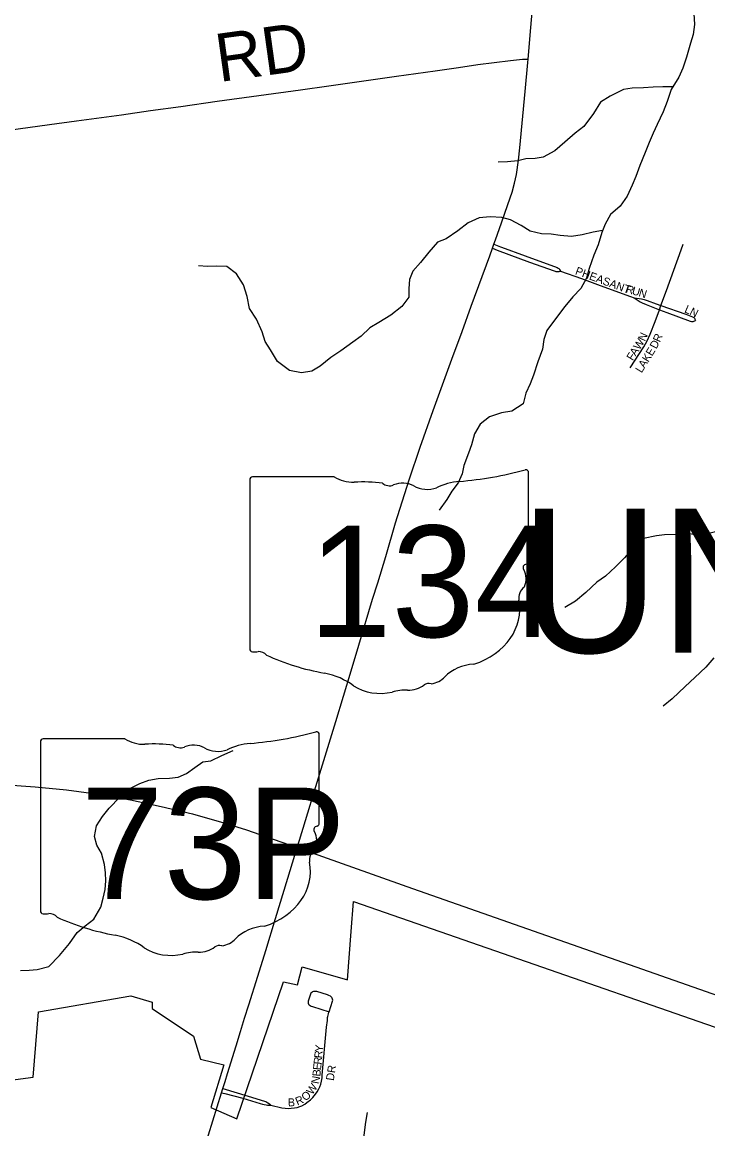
# Model space of a CAD drawing. Extents: x 1442749 to 1756758, y 235267 to 677782.
# Drawn here: x 1593624 to 1597905, y 534274 to 541188 of the extents above; entities that cross this region are included whole.
import ezdxf

# ---------------------------------------------------------------- set-up
doc = ezdxf.new("R2010")
doc.units = 0
for name, color, linetype in [('GM_P_State_Alignment', 7, 'Continuous'), ('GM_P_State_Location', 7, 'Continuous'), ('GM_P_State_Shield', 7, 'Continuous'), ('GM_X_City_Street', 7, 'Continuous'), ('GM_X_City_Street_Text', 7, 'Continuous'), ('GM_X_Corporation', 7, 'Continuous'), ('GM_X_County_Road', 7, 'Continuous'), ('GM_X_County_Road_Text', 7, 'Continuous'), ('GM_X_Minor_River', 7, 'Continuous'), ('GM_X_State_Location', 7, 'Continuous'), ('GM_X_State_Route', 7, 'Continuous'), ('GM_X_State_Shield', 7, 'Continuous'), ('GM_X_Township_Subdivision', 7, 'Continuous'), ('GM_X_Township_Subdivision_Text', 7, 'Continuous'), ('GM_X_Township_Text', 7, 'Continuous')]:
    doc.layers.add(name, color=color, linetype=linetype)

msp = doc.modelspace()

# ---------------------------------------------------------------- linework, layer by layer
at = {"layer": 'GM_P_State_Alignment'}
msp.add_lwpolyline([(1591177.3, 536368.3), (1592540.6, 536412.7), (1592922.9, 536426.3), (1593101.8, 536430.5), (1593301.6, 536434.6), (1593503.4, 536426.3), (1593705.2, 536411.8), (1593900.7, 536393), (1594100.5, 536366), (1594300.2, 536330.6), (1594491.6, 536289), (1594687.2, 536243.2), (1594882.7, 536187.1), (1595024.2, 536143.4), (1595190.6, 536085.1), (1595341.4, 536032.9), (1596060.7, 535775.7), (1599323.3, 534630.8), (1600098.2, 534456.7), (1600484.1, 534379), (1600863.9, 534361), (1601641.5, 534432.8), (1602490.9, 534540.5), (1603334.8, 534713.2)], dxfattribs=at)
at = {"layer": 'GM_P_State_Shield'}
for p, q in [((1595478.6, 536184), (1595478.6, 536736.7)), ((1593738.4, 536692.4), (1593738.4, 535635.7)), ((1594265.2, 536710.5), (1593755.6, 536710.5)), ((1595478.5, 536184.1), (1595478.6, 536184))]:
    msp.add_line(p, q, dxfattribs=at)
for centre, major_axis, start_param, end_param in [((1594858.7, 538151.1), (1845.5, 0), 4.814394, 5.042369), ((1595459.3, 536739), (19.4, 0), 6.141152, 7.989035), ((1593758.4, 536694.6), (20.2, 0), 1.712693, 3.28349), ((1594386.5, 536833.2), (195.5, 0), 4.042523, 4.731795), ((1594451.4, 536117.3), (702, 0), 1.404758, 1.657858), ((1594610.7, 536700.1), (56.4, 0), 3.836095, 5.185415), ((1594693.6, 536578), (117.3, 0), 0.950623, 2.079405), ((1595094.1, 536387.8), (371.3, 0), 1.699011, 2.107814), ((1594844.9, 536745.5), (141.1, 0), 4.081561, 5.145723), ((1595458, 536181.9), (20.7, 0), 5.05454, 6.418171), ((1595474.1, 536143.4), (30, 0), 1.883978, 3.671073), ((1595283.4, 536073.5), (180, 0), 5.934695, 6.695948), ((1595548, 535952.7), (130.9, 0), 2.387724, 3.262537), ((1594962.1, 535882.4), (461.6, 0), 5.101752, 6.440018), ((1593758.5, 535633.4), (20.3, 0), 3.00124, 4.508301), ((1593761.6, 535741.5), (155.2, 0), 4.665946, 4.897461), ((1593793.4, 535574.8), (56, 0), 0.519207, 1.627899), ((1594500, 536524.1), (1332.7, 0), 4.195997, 4.488961), ((1594102.7, 535161), (417, 0), 0.823519, 1.323587), ((1595156.7, 535339.1), (252.8, 0), 1.647645, 2.488434), ((1594725.8, 535490.4), (141, 0), 4.691044, 5.507374), ((1594853.4, 535388.1), (39.7, 0), 1.147584, 2.315152), ((1594836.4, 535533.3), (149.1, 0), 4.937069, 5.64225), ((1594553.6, 535569.5), (264.6, 0), 4.026481, 4.996735), ((1594706.5, 535204.2), (217.4, 0), 1.495662, 1.94098)]:
    msp.add_ellipse(centre, major_axis=major_axis, ratio=0.8, start_param=start_param, end_param=end_param, dxfattribs=at)
at = {"layer": 'GM_X_City_Street'}
for points in [[(1595177, 534422.2), (1595245.6, 534406.7), (1595264.9, 534403.8), (1595287.9, 534402.2), (1595304, 534403), (1595323.7, 534405.2), (1595340.3, 534407.8), (1595358.5, 534414.5), (1595370.4, 534419.2), (1595387.8, 534429), (1595401.9, 534439.3), (1595424, 534455.9), (1595438.5, 534471.1), (1595455.2, 534490.7), (1595465.2, 534505.7), (1595475.8, 534524.1), (1595482.1, 534537.9), (1595488.5, 534554.1), (1595492.8, 534571.8), (1595496.3, 534592.8), (1595497.8, 534609.5), (1595524.3, 534909.3), (1595529.2, 534951.9), (1595531.2, 534969.4), (1595532.3, 534976.5), (1595533.7, 534984.1), (1595536.4, 534992.4), (1595539.5, 535002.4), (1595540.7, 535006.2), (1595562.1, 535071.2), (1595562.8, 535077.5), (1595562.2, 535084.2), (1595559.7, 535090.8), (1595556.3, 535095.6), (1595548.3, 535102.7), (1595539.5, 535107.6), (1595529.6, 535112), (1595462.7, 535131.7), (1595451, 535132.8), (1595443.2, 535132.1), (1595437, 535129.7), (1595431.5, 535126.5), (1595426.9, 535121.6), (1595423.5, 535116.2), (1595409.7, 535072.5), (1595409, 535066.1), (1595409.2, 535059.6), (1595411.6, 535054.2), (1595416.4, 535048.8), (1595421.2, 535044.9), (1595428.2, 535041.5), (1595436.6, 535038.1), (1595540.7, 535006.2)], [(1594877, 534526.5), (1595035.3, 534478.8), (1595135.9, 534448.1), (1595144.3, 534444.6), (1595150.7, 534441.2), (1595157.5, 534437.3), (1595168, 534429.9), (1595177, 534422.2)], [(1594868.7, 534500.3), (1594889.9, 534494.8), (1595000.9, 534465.9), (1595109.5, 534433.3), (1595123.5, 534429.3), (1595135.6, 534425.7), (1595146.5, 534423.5), (1595155.6, 534422.2), (1595164.9, 534421.8), (1595177, 534422.2)], [(1595755.7, 534192.9), (1595757.6, 534218.5), (1595770, 534315.8), (1595780.6, 534376.9)]]:
    msp.add_lwpolyline(points, dxfattribs=at)
at = {"layer": 'GM_X_Corporation'}
msp.add_lwpolyline([(1591592.8, 534218.7), (1591541.7, 534311.9), (1593692.6, 534596.7), (1593726.4, 535006.4), (1594301.4, 535104.8), (1594436.1, 535066.6), (1594435.7, 535026.5), (1594694.2, 534853.4), (1594736.8, 534710.6), (1594883.6, 534673.8), (1594801.6, 534407.2), (1594965.1, 534337.4), (1595254.7, 535192.4), (1595342.6, 535173.4), (1595371.9, 535287.4), (1595655.6, 535205.1), (1595677.5, 535508.1), (1595692.5, 535694.6), (1598975.5, 534553.1), (1599120.4, 534412), (1599138.1, 534392.6), (1599013, 534202.8)], dxfattribs=at)
at = {"layer": 'GM_X_County_Road'}
msp.add_lwpolyline([(1591906.3, 540264.1), (1591949.6, 540271.2), (1592179.2, 540310), (1592576.7, 540378.3), (1592696.3, 540399.1), (1592777.6, 540410.9), (1592982.3, 540438.5), (1593340, 540486.2), (1593794.8, 540549.3), (1593963.9, 540571.7), (1594243.3, 540609.8), (1594425.1, 540635.9), (1594613.5, 540661.9), (1594840.9, 540694.2), (1595360.7, 540765.5), (1595539.3, 540791), (1595961.5, 540850.2), (1596201.8, 540884.2), (1596347.8, 540904.9), (1596467.8, 540923), (1596672.8, 540949.5), (1596748, 540957.1), (1596783.4, 540957.7)], dxfattribs=at)
at = {"layer": 'GM_X_Minor_River'}
for points in [[(1597817.9, 541242.4), (1597821.1, 541174.2), (1597812.3, 541110.1), (1597795.6, 541056.1), (1597772.5, 540970.2), (1597749.7, 540900.2), (1597722.9, 540844.4), (1597675.9, 540766.7), (1597651, 540692.8), (1597626.2, 540628.9), (1597589.2, 540549.1), (1597562.5, 540495.2), (1597537.7, 540435.3), (1597512.9, 540373.5), (1597479.9, 540291.6), (1597455, 540223.7), (1597432.3, 540169.8), (1597401.4, 540102), (1597356.6, 540038.3), (1597297.9, 539986.8), (1597263.1, 539927.1), (1597242.4, 539873.1), (1597219.4, 539797.2), (1597192.6, 539733.3), (1597163.6, 539649.4), (1597146.8, 539589.4), (1597112, 539523.7), (1597061.2, 539472.1), (1597012.4, 539412.5), (1596947.3, 539327), (1596900.4, 539261.3), (1596881.7, 539205.4), (1596873, 539145.3), (1596844, 539065.4), (1596816.9, 538983.5), (1596796.2, 538929.6), (1596767.5, 538869.8), (1596752.7, 538803.8), (1596682, 538758.4), (1596615.7, 538747.2), (1596541.2, 538721.9), (1596482.6, 538676.5), (1596447.8, 538616.7), (1596428.9, 538546.7), (1596410.3, 538494.8), (1596381.3, 538418.9), (1596370.7, 538366.9), (1596345.9, 538311), (1596307.2, 538257.3), (1596274.5, 538205.5), (1596227.7, 538139.9)], [(1597687, 540785), (1597624, 540783.3), (1597563.9, 540782), (1597503.7, 540778.7), (1597431.5, 540775.5), (1597377.3, 540768.1), (1597294.6, 540724.9), (1597234, 540687.5), (1597191.1, 540617.8), (1597130, 540536.3), (1597077.4, 540494.8), (1597012.6, 540439.4), (1596949.8, 540383.9), (1596877.2, 540344.6), (1596827, 540337.2), (1596768.9, 540333.8), (1596718.6, 540322.4), (1596654.4, 540315.1), (1596596.3, 540313.8)], [(1597247.7, 539887), (1597188.3, 539875.8), (1597120, 539858.5), (1597053.7, 539849.2), (1596983.6, 539856), (1596927.6, 539862.7), (1596865.5, 539865.4), (1596795.6, 539882.3), (1596739.8, 539917), (1596672.1, 539953.9), (1596618.2, 539968.5), (1596546.1, 539971.4), (1596477.9, 539966.1), (1596409.3, 539934.8), (1596344.6, 539885.4), (1596271.9, 539834.1), (1596217.5, 539812.7), (1596162.6, 539751.1), (1596109.8, 539687.6), (1596063, 539631.9), (1596042.3, 539580), (1596037.7, 539523.9), (1596039, 539469.8), (1595994.3, 539412.1), (1595925.5, 539356.8), (1595850.8, 539311.5), (1595794.2, 539278), (1595739.5, 539226.5), (1595689, 539189), (1595614.2, 539135.7), (1595551.5, 539092.3), (1595484.7, 539038.9), (1595432.3, 539007.4), (1595368, 538998.1), (1595292, 539013), (1595218.5, 539068), (1595175.3, 539140.7), (1595141.8, 539193.2), (1595122.5, 539253.6), (1595087.4, 539332.2), (1595044.1, 539398.9), (1595028.9, 539475.3), (1595005.8, 539547.8), (1594962.5, 539616.5), (1594900.9, 539661.3), (1594838.8, 539664), (1594780.6, 539662.7), (1594724.6, 539665.3)], [(1597971.8, 538007.6), (1597901.5, 537992.4), (1597833.2, 537985.1), (1597771.2, 537993.8), (1597705, 537986.6), (1597634.8, 537985.4), (1597584.7, 537979.9), (1597502.3, 537962.8), (1597451.7, 537921.3), (1597384.6, 537841.8), (1597327.8, 537786.3), (1597265, 537726.9), (1597212.4, 537689.4), (1597143.5, 537626), (1597078.7, 537570.6), (1597012.1, 537531.2)], [(1597942.4, 537217.7), (1597891.6, 537158.1), (1597822.7, 537094.7), (1597763.9, 537037.2), (1597682.8, 536959.9), (1597626.1, 536914.5)], [(1594359.4, 536432.4), (1594413.8, 536451.9), (1594472, 536463.2), (1594544.2, 536464.4), (1594598.4, 536471.8), (1594650.8, 536495.3), (1594701.3, 536532.8), (1594751.8, 536566.3), (1594802, 536573.8), (1594870.6, 536607.1), (1594941.1, 536638.4)], [(1593614, 535263.7), (1593668.1, 535265), (1593718.3, 535270.5), (1593790.6, 535287.7), (1593857.6, 535357.1), (1593918.6, 535432.6), (1593967.5, 535500.3), (1594018.1, 535541.8), (1594070.7, 535585.3), (1594115.7, 535659), (1594130.4, 535715), (1594141.1, 535769), (1594145.7, 535823.2), (1594144.3, 535873.3), (1594136.9, 535925.5), (1594119.7, 535995.9), (1594090.3, 536046.4), (1594074.9, 536100.7), (1594087.7, 536166.8), (1594124.5, 536226.5), (1594167.2, 536278.2), (1594234.1, 536345.6), (1594305, 536405), (1594359.4, 536432.4)]]:
    msp.add_lwpolyline(points, dxfattribs=at)
at = {"layer": 'GM_X_State_Route'}
for points in [[(1595094.5, 535228), (1595144.3, 535388.4), (1595205.7, 535589.1), (1595283, 535839.8), (1595341.4, 536032.9), (1595355.3, 536078.4), (1595392.3, 536200.9), (1595457.6, 536414.2), (1595581.3, 536818.9), (1595677.1, 537136.1), (1595726, 537296.1), (1595812, 537583.7), (1595843.7, 537686.2), (1595894.2, 537849.8), (1595955.7, 538059.4), (1596040.9, 538328.4), (1596109, 538532.8), (1596190.5, 538762.8), (1596306.4, 539083.7), (1596370.3, 539255.9), (1596427.8, 539413.1), (1596542.7, 539727.3), (1596560.2, 539776.4), (1596568.8, 539800.7), (1596579, 539829.2), (1596616, 539934.3), (1596656.8, 540048.6), (1596682.6, 540126.2), (1596698.1, 540182.9), (1596709.2, 540237.2), (1596721.7, 540325.4), (1596730.3, 540402.8), (1596765, 540755.4), (1596781.4, 540935.4), (1596783.4, 540957.7), (1596800.2, 541154), (1596816.8, 541346.8)], [(1595012.5, 534965.8), (1595039.3, 535050), (1595094.5, 535228)], [(1594906.7, 534620.3), (1594959, 534792.8), (1594987.6, 534883.3), (1595012.5, 534965.8)], [(1594891.1, 534570.9), (1594906.7, 534620.3)], [(1594476.5, 533210.3), (1594479.2, 533224.7), (1594482.8, 533242.8), (1594487.8, 533262.8), (1594493.3, 533281.3), (1594515.6, 533356.1), (1594549.8, 533470.6), (1594564.6, 533516.9), (1594607, 533649.2), (1594626.3, 533710.3), (1594662, 533822.9), (1594671, 533851.6), (1594706.9, 533966.6), (1594737.1, 534069.8), (1594760.3, 534149.1), (1594868.7, 534500.3), (1594877, 534526.5), (1594891.1, 534570.9)]]:
    msp.add_lwpolyline(points, dxfattribs=at)
at = {"layer": 'GM_X_State_Shield'}
for p, q in [((1595045.2, 538329.2), (1595045.2, 537272.5)), ((1595572, 538347.3), (1595062.3, 538347.3)), ((1596785.4, 537820.8), (1596785.4, 538373.5)), ((1596785.2, 537820.9), (1596785.4, 537820.8))]:
    msp.add_line(p, q, dxfattribs=at)
for centre, major_axis, start_param, end_param in [((1596165.5, 539787.9), (1845.5, 0), 4.814394, 5.042369), ((1596766.1, 538375.8), (19.4, 0), 6.141152, 7.989035), ((1595065.2, 538331.4), (20.2, 0), 1.712693, 3.28349), ((1595693.3, 538470), (195.5, 0), 4.042523, 4.731795), ((1595758.2, 537754.1), (702, 0), 1.404758, 1.657858), ((1596400.9, 538024.6), (371.3, 0), 1.699011, 2.107814), ((1595917.5, 538336.9), (56.4, 0), 3.836095, 5.185415), ((1596000.4, 538214.8), (117.3, 0), 0.950623, 2.079405), ((1596151.7, 538382.3), (141.1, 0), 4.081561, 5.145723), ((1596780.9, 537780.2), (30, 0), 1.883978, 3.671073), ((1596590.2, 537710.3), (180, 0), 5.934695, 6.695948), ((1596764.7, 537818.7), (20.7, 0), 5.05454, 6.418171), ((1596854.8, 537589.5), (130.9, 0), 2.387724, 3.262537), ((1596268.9, 537519.2), (461.6, 0), 5.101752, 6.440018), ((1595065.3, 537270.2), (20.3, 0), 3.00124, 4.508301), ((1595068.4, 537378.3), (155.2, 0), 4.665946, 4.897461), ((1595100.2, 537211.6), (56, 0), 0.519207, 1.627899), ((1595806.8, 538160.9), (1332.7, 0), 4.195997, 4.488961), ((1596463.5, 536975.9), (252.8, 0), 1.647645, 2.488434), ((1595409.5, 536797.8), (417, 0), 0.823519, 1.323587), ((1596143.2, 537170.1), (149.1, 0), 4.937069, 5.64225), ((1595860.4, 537206.3), (264.6, 0), 4.026481, 4.996735), ((1596013.3, 536841), (217.4, 0), 1.495662, 1.94098), ((1596032.6, 537127.2), (141, 0), 4.691044, 5.507374), ((1596160.2, 537024.9), (39.7, 0), 1.147584, 2.315152)]:
    msp.add_ellipse(centre, major_axis=major_axis, ratio=0.8, start_param=start_param, end_param=end_param, dxfattribs=at)
at = {"layer": 'GM_X_Township_Subdivision'}
for points in [[(1596560.2, 539776.4), (1596590.2, 539764.7), (1596663.3, 539736.4), (1596792.2, 539689.1), (1596946.1, 539634.2), (1596951.4, 539632.3), (1596955.2, 539630.9), (1596959.5, 539630.1), (1596964.2, 539630.1), (1596970.2, 539630.7), (1596976.4, 539631.4), (1596984, 539632.7)], [(1596568.8, 539800.7), (1596609.6, 539785), (1596615.8, 539782.7), (1596764.1, 539728.9), (1596965.1, 539654.6), (1596971.1, 539651.9), (1596974.6, 539649.2), (1596978, 539645.4), (1596979.7, 539642.1), (1596984, 539632.7)], [(1597612.2, 539417.9), (1597645.9, 539512.3), (1597738.3, 539765), (1597751.3, 539802.1)], [(1596984, 539632.7), (1597115.4, 539586.6), (1597232, 539543.6), (1597422.9, 539475.1), (1597444.3, 539466.9)], [(1597444.3, 539466.9), (1597481.6, 539441.2), (1597494.5, 539435), (1597520.7, 539424.1), (1597602.9, 539391.9)], [(1597444.3, 539466.9), (1597490.9, 539458.7), (1597507.4, 539454.8), (1597525.7, 539449.4), (1597582.3, 539428.4), (1597612.2, 539417.9)], [(1597419.9, 539028.4), (1597505.8, 539160.2), (1597526.7, 539197), (1597545.6, 539238.4), (1597576.4, 539317.6), (1597602.9, 539391.9)], [(1597602.9, 539391.9), (1597612.2, 539417.9)], [(1597602.9, 539391.9), (1597649.4, 539373.7), (1597794.4, 539320.7), (1597802.8, 539318.9), (1597812.5, 539318.1), (1597817.9, 539319.2), (1597823.2, 539322.1), (1597827.9, 539325)], [(1597612.2, 539417.9), (1597768.3, 539363.2), (1597809.3, 539346.5), (1597816.8, 539342.2), (1597820.7, 539337.9), (1597823.6, 539333.2), (1597827.9, 539325)]]:
    msp.add_lwpolyline(points, dxfattribs=at)

# ---------------------------------------------------------------- texts
at = {"layer": 'GM_P_State_Location'}
for s in ['s', 'r']:
    msp.add_text(s, height=1, dxfattribs=at).set_placement((1594589, 536093.8))
msp.add_text('73P', height=1, rotation=0.00001, dxfattribs=at).set_placement((1594213.9, 536021.1))
at = {"layer": 'GM_P_State_Shield'}
msp.add_text('73P', height=696.1, dxfattribs=at).set_placement((1593989.4, 535710.2))
at = {"layer": 'GM_X_City_Street_Text'}
for s, rotation, p in [('Y', 84.28505, (1595500.4, 534753)), ('R', 84.28457, (1595492.5, 534674.2)), ('R', 84.28964, (1595496.4, 534713.6)), ('E', 84.30067, (1595489, 534639.2)), ('DR', 81.03381, (1595569, 534572.8)), ('N', 79.96785, (1595476.8, 534552.3)), ('B', 84.2793, (1595485.1, 534599.7)), ('W', 55.12851, (1595435.2, 534483.7)), ('B', 2.47795, (1595283.7, 534414.2)), ('R', 22.6293, (1595341.9, 534420)), ('O', 41.59146, (1595393.7, 534444.8))]:
    msp.add_text(s, height=50, rotation=rotation, dxfattribs=at).set_placement(p)
at = {"layer": 'GM_X_County_Road_Text'}
msp.add_text('RD', height=300, rotation=7.92032, dxfattribs=at).set_placement((1594853.3, 540813.6))
at = {"layer": 'GM_X_State_Location'}
for s in ['s', 'r']:
    msp.add_text(s, height=1, dxfattribs=at).set_placement((1595895.7, 537730.6))
msp.add_text('134', height=1, rotation=0.00001, dxfattribs=at).set_placement((1595542.8, 537657.8))
at = {"layer": 'GM_X_State_Shield'}
msp.add_text('134', height=696.1, dxfattribs=at).set_placement((1595412.1, 537347))
at = {"layer": 'GM_X_Township_Subdivision_Text'}
for s, rotation, p in [('PHEASANT', 339.81224, (1597072.8, 539614.4)), ('R', 343.70775, (1597389, 539500.2)), ('U', 343.73385, (1597427, 539489)), ('N', 342.78158, (1597469, 539476.8)), ('L', 336.62563, (1597754.7, 539376.8)), ('N', 333.59134, (1597786.4, 539363.1)), ('W', 57.7703, (1597477.9, 539136.4)), ('N', 64.59372, (1597511.5, 539190.5)), ('R', 66.10123, (1597604.9, 539184.9)), ('A', 57.73505, (1597454.4, 539099.2)), ('E', 58.6477, (1597556.3, 539098.2)), ('D', 62.52336, (1597583.2, 539142.8)), ('F', 57.75717, (1597435.6, 539069.4)), ('K', 58.19132, (1597532.8, 539060.4)), ('L', 58.15094, (1597491, 538993.1)), ('A', 58.11044, (1597509.6, 539023))]:
    msp.add_text(s, height=50, rotation=rotation, dxfattribs=at).set_placement(p)
at = {"layer": 'GM_X_Township_Text'}
msp.add_text('UNION', height=900, rotation=0.00001, dxfattribs=at).set_placement((1596733.3, 537249.5))

doc.saveas('drawing.dxf')
